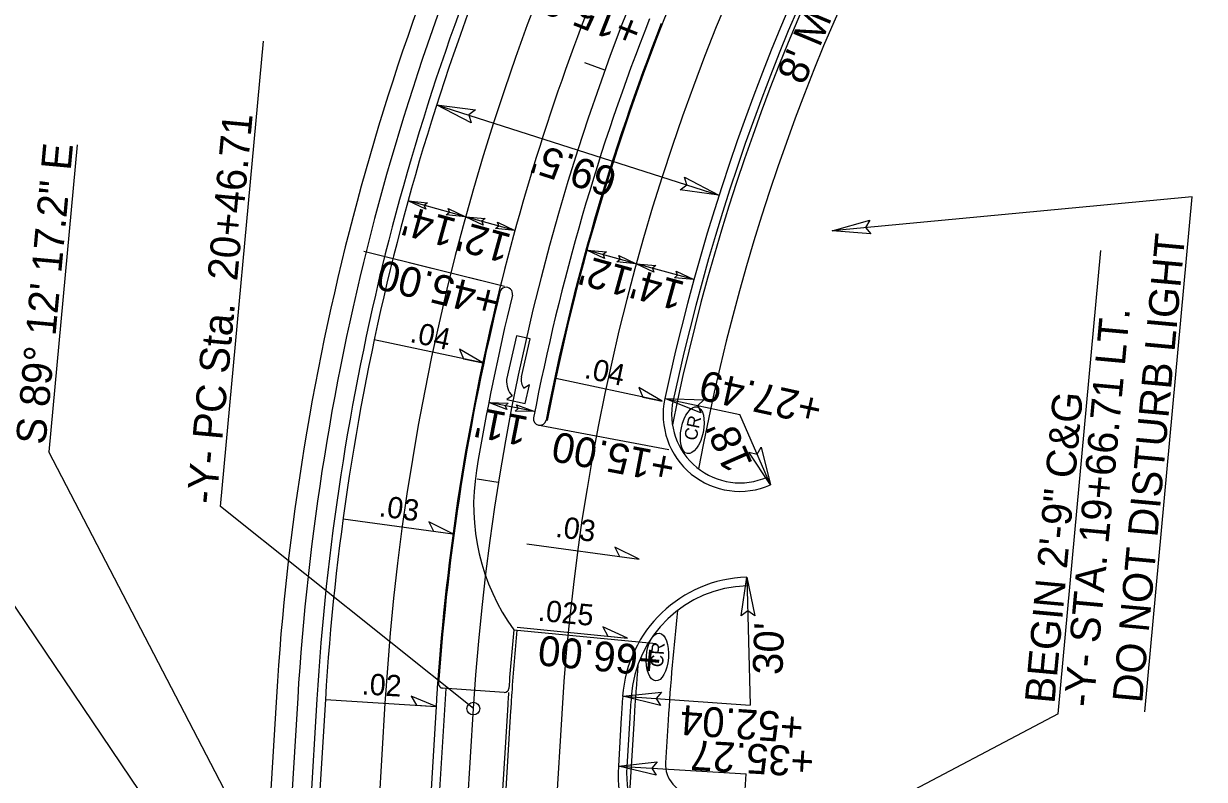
# Model space of a CAD drawing. Extents: x 2010838 to 2015151, y 441905 to 447792.
# Drawn here: x 2011964.2 to 2012241, y 445465.4 to 445642.5 of the extents above; entities that cross this region are included whole.
import ezdxf

# ---------------------------------------------------------------- set-up
doc = ezdxf.new("R2010")
doc.units = 0
for name, color, linetype in [('A-Wall-Abov', 7, 'Continuous'), ('A-Wall-Blow', 7, 'Continuous'), ('A-Wall-Comp', 7, 'Continuous'), ('C-Building', 7, 'Continuous'), ('C-CURB STOPS', 7, 'Continuous'), ('C-Grave Plots', 7, 'Continuous'), ('C-Profile', 7, 'Continuous'), ('CLRD', 7, 'Continuous'), ('Cont-2-Lidar', 7, 'Continuous'), ('DEED', 7, 'Continuous'), ('Default_10ft_LIDAR_Contou', 7, 'Continuous'), ('HATCH', 7, 'Continuous'), ('s-Existing Major', 7, 'Continuous'), ('S-Existing Minor', 7, 'Continuous'), ('S-overhead electric', 7, 'Continuous'), ('TEXT-LG', 7, 'Continuous'), ('TEXT-MED', 7, 'Continuous'), ('X4', 7, 'Continuous')]:
    doc.layers.add(name, color=color, linetype=linetype)

msp = doc.modelspace()

# ---------------------------------------------------------------- linework, layer by layer
at = {"layer": 'A-Wall-Abov'}
for p, q in [((2012079.7, 445569.39), (2012077.42, 445559.09)), ((2012082.92, 445568.68), (2012079.7, 445569.39)), ((2012080.94, 445559.75), (2012082.92, 445568.68)), ((2012082.78, 445557.85), (2012081.52, 445557.06)), ((2012081.75, 445553.47), (2012082.78, 445557.85)), ((2012078.72, 445555.27), (2012077.47, 445554.47)), ((2012077.47, 445554.47), (2012081.75, 445553.47))]:
    msp.add_line(p, q, dxfattribs=at)
for centre, radius, start, end in [((2012082.64, 445558.75), 5.25, 176.187, 221.4987), ((2012084.12, 445559.03), 3.27, 167.511, 217.1691)]:
    msp.add_arc(centre, radius, start, end, dxfattribs=at)
at = {"layer": 'A-Wall-Blow'}
for p, q in [((2012071.81, 445563.01), (2012046.38, 445568.42)), ((2012113.87, 445554.06), (2012088.92, 445559.37)), ((2012039.08, 445526.47), (2012064.84, 445522.97)), ((2012082.18, 445520.62), (2012108.49, 445517.04)), ((2012079.9, 445501.08), (2012105.78, 445498.54)), ((2012034.93, 445484.09), (2012060.88, 445482.52))]:
    msp.add_line(p, q, dxfattribs=at)
at = {"layer": 'A-Wall-Comp'}
for points in [[(2012071.81, 445563.01), (2012066.36, 445566.22), (2012067.28, 445563.97)], [(2012113.87, 445554.06), (2012108.42, 445557.27), (2012109.35, 445555.02)], [(2012064.84, 445522.97), (2012059.16, 445525.76), (2012060.26, 445523.59)], [(2012108.49, 445517.04), (2012102.82, 445519.83), (2012103.91, 445517.67)], [(2012105.78, 445498.54), (2012100, 445501.12), (2012101.17, 445498.99)], [(2012060.88, 445482.52), (2012055.01, 445484.88), (2012056.27, 445482.8)]]:
    msp.add_lwpolyline(points, close=True, dxfattribs=at)
at = {"layer": 'C-Building'}
for p, q in [((2012100.48, 445631.62), (2012095.78, 445633.32)), ((2012075.46, 445534.95), (2012070.53, 445535.74))]:
    msp.add_line(p, q, dxfattribs=at)
at = {"layer": 'C-CURB STOPS'}
msp.add_line((2012076.88, 445485.8), (2012062.41, 445486.79), dxfattribs=at)
for centre, radius, start, end in [((2012603.65, 445449.83), 529.5, 158.5298, 169.0786), ((2012603.65, 445449.83), 526.5, 158.5298, 169.0786), ((2012603.65, 445449.83), 543.5, 166.1871, 175.9877), ((2012077.32, 445579.24), 1.5, 346.1871, 166.1871), ((2012603.65, 445449.83), 540.5, 166.1871, 170.6352), ((2012085.21, 445549.87), 1.5, 169.0786, 349.0786), ((2012119.69, 445529.65), 50, 170.6352, 215.7092), ((2012603.65, 445449.83), 527, 174.4869, 175.9848), ((2012062.48, 445487.79), 1, 175.9877, 266.0934), ((2012076.94, 445486.8), 1, 266.0934, 355.9848)]:
    msp.add_arc(centre, radius, start, end, dxfattribs=at)
at = {"layer": 'C-Profile'}
msp.add_line((2012063.14, 445486.74), (2012058.07, 445402.55), dxfattribs=at)
at = {"layer": 'CLRD'}
msp.add_line((2012051.97, 445189.02), (2012069.62, 445482), dxfattribs=at)
msp.add_arc((2012603.65, 445449.83), 535, 123.0111, 176.5533, dxfattribs=at)
at = {"layer": 'DEED'}
msp.add_line((2012077.6, 445481.52), (2012063.82, 445252.61), dxfattribs=at)
msp.add_arc((2012603.65, 445449.83), 527, 176.0934, 176.5533, dxfattribs=at)
at = {"layer": 'Default_10ft_LIDAR_Contou'}
for p, q in [((2012010.36, 445529.36), (2012020.39, 445638.43)), ((2011976.72, 445614.15), (2011970.1, 445542.15)), ((2012036.67, 445414.23), (2011970.1, 445542.15)), ((2012024.02, 445414.41), (2011944.05, 445532.71)), ((2012069.62, 445482), (2012010.36, 445529.36))]:
    msp.add_line(p, q, dxfattribs=at)
msp.add_circle((2012069.62, 445482), 1.5, dxfattribs=at)
msp.add_circle((2012069.62, 445482), 1.5, dxfattribs=at)
at = {"layer": 'HATCH'}
for p, q in [((2012048.9, 445483.24), (2012030.81, 445182.86)), ((2012090.33, 445480.75), (2012074.81, 445223.09))]:
    msp.add_line(p, q, dxfattribs=at)
for radius, start, end in [(555.75, 123.0111, 176.5533), (514.25, 123.0111, 176.5533), (543.75, 147.8308, 166.1871), (526.25, 152.7578, 169.0786), (543.75, 166.1871, 176.0934), (526.25, 174.4869, 176.0934)]:
    msp.add_arc((2012603.65, 445449.83), radius, start, end, dxfattribs=at)
at = {"layer": 's-Existing Major'}
for points in [[(2012069.12, 445619.31), (2012061.02, 445623.53), (2012070.13, 445622.3), (2012068.55, 445621.13)], [(2012119.12, 445606.57), (2012127.21, 445602.35), (2012118.11, 445603.58), (2012119.69, 445604.75)], [(2012058.45, 445599.04), (2012054.31, 445600.98), (2012058.89, 445600.56), (2012058.12, 445599.94)], [(2012063.68, 445599.21), (2012067.81, 445597.27), (2012063.24, 445597.7), (2012064, 445598.32)], [(2012071.95, 445595.33), (2012067.81, 445597.27), (2012072.39, 445596.84), (2012071.62, 445596.22)], [(2012162.82, 445593.3), (2012153.71, 445594), (2012162.57, 445596.44), (2012161.57, 445594.74)], [(2012075.25, 445596.03), (2012079.38, 445594.09), (2012074.81, 445594.52), (2012075.57, 445595.13)], [(2012100.39, 445587.5), (2012096.26, 445589.44), (2012100.83, 445589.02), (2012100.06, 445588.4)], [(2012103.69, 445588.2), (2012107.83, 445586.26), (2012103.25, 445586.69), (2012104.02, 445587.31)], [(2012111.96, 445584.32), (2012107.83, 445586.26), (2012112.4, 445585.83), (2012111.63, 445585.21)], [(2012117.19, 445584.49), (2012121.32, 445582.55), (2012116.75, 445582.98), (2012117.52, 445583.59)], [(2012122.99, 445551.28), (2012114.51, 445554.68), (2012123.69, 445554.35), (2012122.23, 445553.02)], [(2012077.49, 445552.08), (2012073.22, 445553.71), (2012077.82, 445553.62), (2012077.1, 445552.95)], [(2012079.75, 445553.22), (2012084.02, 445551.59), (2012079.42, 445551.68), (2012080.14, 445552.35)], [(2012137.13, 445543.28), (2012139.32, 445534.41), (2012134.23, 445542.07), (2012136.15, 445541.65)], [(2012132.43, 445503.73), (2012133.73, 445512.77), (2012135.58, 445503.77), (2012133.95, 445504.87)], [(2012113.5, 445482.71), (2012104.63, 445484.88), (2012113.77, 445485.84), (2012112.51, 445484.33)], [(2012112.51, 445466.41), (2012103.62, 445468.49), (2012112.75, 445469.55), (2012111.5, 445468.02)]]:
    msp.add_lwpolyline(points, close=True, dxfattribs=at)
at = {"layer": 'S-Existing Minor'}
for p, q in [((2012061.02, 445623.53), (2012127.21, 445602.35)), ((2012238.16, 445601.98), (2012153.71, 445594)), ((2012227.05, 445481.24), (2012238.16, 445601.98)), ((2012067.81, 445597.27), (2012054.31, 445600.98)), ((2012079.38, 445594.09), (2012067.81, 445597.27)), ((2012076.95, 445580.89), (2012043.92, 445589.11)), ((2012107.83, 445586.26), (2012096.26, 445589.44)), ((2012206.76, 445480.76), (2012216.74, 445589.37)), ((2012076.95, 445580.89), (2012054.54, 445586.47)), ((2012121.32, 445582.55), (2012107.83, 445586.26)), ((2012114.51, 445554.68), (2012132.11, 445550.91)), ((2012084.02, 445551.59), (2012073.22, 445553.71)), ((2012139.32, 445534.41), (2012132.11, 445550.91)), ((2012115.44, 445542.62), (2012085.51, 445548.3)), ((2012133.73, 445512.77), (2012134.55, 445482.78)), ((2012079.09, 445500.46), (2012112.5, 445497.24)), ((2012104.63, 445484.88), (2012134.55, 445482.78)), ((2012206.76, 445480.76), (2012058.07, 445402.55)), ((2012103.62, 445468.49), (2012133.56, 445466.69)), ((2012131.76, 445436.74), (2012133.56, 445466.69))]:
    msp.add_line(p, q, dxfattribs=at)
at = {"layer": 'S-overhead electric'}
for p, q in [((2012034.93, 445484.09), (2012032.91, 445450.59)), ((2012060.88, 445482.52), (2012041.32, 445157.71)), ((2012078.35, 445481.47), (2012062.68, 445221.3)), ((2012104.3, 445479.91), (2012103.62, 445468.49))]:
    msp.add_line(p, q, dxfattribs=at)
for centre, radius, start, end in [((2012603.65, 445449.83), 500.25, 126.2999, 167.9015), ((2012603.65, 445449.83), 569.75, 155.3638, 176.5533), ((2012132.11, 445550.91), 18, 167.9015, 293.6058), ((2012134.55, 445482.78), 30, 91.5775, 175.9822), ((2012603.65, 445449.83), 543.75, 176.0934, 176.5533), ((2012603.65, 445449.83), 526.25, 176.0934, 176.5533), ((2012603.65, 445449.83), 500.25, 175.9822, 176.5533), ((2012133.56, 445466.69), 30, 176.5533, 266.5533)]:
    msp.add_arc(centre, radius, start, end, dxfattribs=at)
at = {"layer": 'TEXT-LG'}
for p, q in [((2012023.45, 445484.78), (2012020.31, 445432.69)), ((2012028.44, 445484.48), (2012025.6, 445437.34)), ((2012107.3, 445479.73), (2012106.16, 445460.91)), ((2012115.28, 445479.25), (2012114.68, 445469.27))]:
    msp.add_line(p, q, dxfattribs=at)
for centre, radius, start, end in [((2012603.65, 445449.83), 497.25, 125.5092, 168.553), ((2012603.65, 445449.83), 489.25, 124.1314, 169.5987), ((2012603.65, 445449.83), 581.25, 153.32406, 176.55328), ((2012603.65, 445449.83), 576.25, 153.88004, 176.55328), ((2012603.65, 445449.83), 489.25, 173.5252, 176.5533), ((2012603.65, 445449.83), 497.25, 175.1034, 176.5533), ((2012121.67, 445468.85), 7, 176.5533, 264.9431)]:
    msp.add_arc(centre, radius, start, end, dxfattribs=at)
at = {"layer": 'TEXT-MED'}
for p, q in [((2012032.93, 445484.21), (2012030.92, 445450.71)), ((2012106.3, 445479.79), (2012105.61, 445468.37))]:
    msp.add_line(p, q, dxfattribs=at)
for centre, radius, start, end in [((2012603.65, 445449.83), 498.25, 126.2999, 167.9015), ((2012603.65, 445449.83), 571.75, 155.3638, 176.5533), ((2012132.11, 445550.91), 16, 167.9015, 293.6058), ((2012134.55, 445482.78), 28, 91.5775, 175.9822), ((2012603.65, 445449.83), 498.25, 175.9822, 176.5533), ((2012133.56, 445466.69), 28, 176.5533, 266.5533)]:
    msp.add_arc(centre, radius, start, end, dxfattribs=at)
at = {"layer": 'X4'}
for centre, major_axis in [((2012120.94, 445547.25), (1.14, 5.49)), ((2012112.77, 445494.07), (0.42, 5.59))]:
    msp.add_ellipse(centre, major_axis=major_axis, ratio=0.462467, dxfattribs=at)

# ---------------------------------------------------------------- texts
at = {"layer": 'A-Wall-Blow'}
for s, rotation, p in [('.04', 347.9862, (2012054.53, 445567.96)), ('.04', 347.9862, (2012095.43, 445559.53)), ('.03', 352.27, (2012047.32, 445527.1)), ('.03', 352.27, (2012088.7, 445522.28)), ('.025', 354.4119, (2012084.61, 445502.62)), ('.02', 356.5533, (2012043.36, 445485.34))]:
    msp.add_text(s, height=5, rotation=rotation, dxfattribs=at).set_placement(p)
at = {"layer": 'C-Grave Plots'}
for s, rotation, p in [("8' MUP", 67.4047, (2012147.11, 445627.91)), ('+15.00', 158.5298, (2012109.69, 445643.14)), ("69.5'", 162.2493, (2012103.8, 445608.4)), ("14'", 164.6154, (2012066.03, 445596.66)), ("12'", 164.6154, (2012078.88, 445593.04)), ('+45.00', 166.0264, (2012076.14, 445580.31)), ("12'", 164.6154, (2012107.51, 445585.08)), ("14'", 164.6154, (2012119.56, 445581.89)), ('+27.49', 167.6235, (2012151.83, 445555.16)), ("11'", 168.9197, (2012082.86, 445550.28)), ('+15.00', 169.2393, (2012117.28, 445541.58)), ("18'", 113.6058, (2012135.22, 445539.36)), ("30'", 87.8627, (2012142.07, 445489.81)), ('+66.00', 174.4869, (2012113.96, 445496.39)), ('+52.04', 176.0175, (2012147.2, 445480.84)), ('+35.27', 176.5533, (2012149.65, 445472.88))]:
    msp.add_text(s, height=7, rotation=rotation, dxfattribs=at).set_placement(p)
at = {"layer": 'Cont-2-Lidar'}
msp.add_text('S 89%%d 12\' 17.2" E', height=7, rotation=84.7467, dxfattribs=at).set_placement((2011969.31, 445543.7))
at = {"layer": 'Default_10ft_LIDAR_Contou'}
msp.add_text('-Y- PC Sta.  20+46.71', height=7, rotation=84.6457, dxfattribs=at).set_placement((2012009.34, 445529.77))
at = {"layer": 'S-Existing Minor'}
for s, p in [('DO NOT DISTURB LIGHT', (2012226.41, 445483.15)), ('-Y- STA. 19+66.71 LT.', (2012214.98, 445482.16)), ('BEGIN 2\'-9" C&G ', (2012205.85, 445483))]:
    msp.add_text(s, height=7, rotation=84.7467, dxfattribs=at).set_placement(p)
at = {"layer": 'X4'}
for rotation, p in [(78.254, (2012121.9, 445544.64)), (85.6623, (2012114.06, 445491.61))]:
    msp.add_text('CR', height=3, rotation=rotation, dxfattribs=at).set_placement(p)

doc.saveas('drawing.dxf')
